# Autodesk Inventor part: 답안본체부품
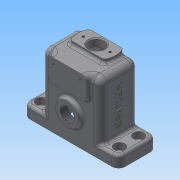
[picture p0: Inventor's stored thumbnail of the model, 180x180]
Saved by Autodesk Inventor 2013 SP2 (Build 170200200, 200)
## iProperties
Created: 2023-12
Part Number: 답안본체부품
Material: Generic
Document SubType Name: Modeling
Designer: i
Density: 1 g/cm^3
Author: i
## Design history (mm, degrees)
sketch "스케치1"
  geometry: L1 (-50, 20)-(50, 20); L2 (50, 20)-(50, -20); L3 (50, -20)-(-50, -20); L4 (-50, -20)-(-50, 20); L5 (-50, 20)-(50, -20); L6 (50, 20)-(-50, -20); 1 further point
  constraints: 12 end point, 2 midpoint, 2 parallel, 1 horizontal, 1 perpendicular
  dimensions: "d0" = 100 distance of L2.end L3.end; "d1" = 40 distance of L1.end L2.end
extrude "돌출1" new body sketch "스케치1" distance "d2" = 12; taper "d3" = 0 deg
sketch "스케치2"
  geometry: L1 (50, 12)-(50, 0) reference; L2 (50, 0)-(-50, 0) reference; L3 (-50, 0)-(-50, 12) reference; L4 (-50, 12)-(50, 12) reference; L5 (50, 12)-(-50, 12) reference; L6 (-31, 12)-(31, 12); L7 (31, 12)-(31, 72); L8 (31, 72)-(-31, 72); L9 (-31, 72)-(-31, 12); 3 further points
  constraints: 8 end point, 2 midpoint, 2 parallel, 1 horizontal, 1 perpendicular, 1 point on line, 1 vertical alignment
  dimensions: "d4" = 62 distance of L7.end L8.end; "d6" = 72 distance between parallel lines of L8 L2
extrude "돌출2" join sketch "스케치2" stored distance "d7" = 40; taper "d9" = 0 deg; dims "d8" = 20, "d10" = 0
sketch "스케치3"
  geometry: L1 (-31, -72)-(31, -72) reference; L2 (20, -72)-(-20, -72); L3 (-20, -72)-(-20, -48); L4 (-20, -48)-(20, -48); L5 (20, -48)-(20, -72); 3 further points
  constraints: 8 end point, 2 midpoint, 2 parallel, 1 horizontal, 1 perpendicular, 1 point on line, 1 vertical alignment
  dimensions: "d11" = 40 distance of L3.end L4.end; "d13" = 24 distance of L2.end L3.end
extrude "돌출3" join sketch "스케치3" distance "d14" = 4; taper "d15" = 0 deg
sketch "스케치4"
  geometry: L1 (0, 0)-(100, 0) reference; L2 (0, -12)-(0, 0) reference; L3 (0, 0)-(100, 0) reference; L4 (100, 0)-(100, -12) reference; L5 (100, -12)-(81, -12) reference; L6 (81, -12)-(81, -72) reference; L7 (81, -72)-(70, -72) reference; L8 (70, -72)-(30, -72) reference; L9 (30, -72)-(19, -72) reference; L10 (19, -72)-(19, -12) reference; L11 (19, -12)-(0, -12) reference; L12 (70, -48)-(70, -72) reference; L13 (30, -48)-(70, -48) reference; L14 (30, -72)-(30, -48) reference; C1 r 12 at (50, -28); 1 further point
  constraints: 1 centre point
  dimensions: "d16" = 28 distance from line of L1 C1.centre; "d17" = 24 diameter of C1
extrude "돌출4" join sketch "스케치4" distance "d18" = 4; taper "d19" = 0 deg
sketch "스케치5"
  geometry: L1 (11, 44)-(51, 44) reference; L2 (55, 3)-(48.321, 3); L3 (7, 3)-(7, 23); L4 (7, 23)-(13.679, 23); L5 (55, 23)-(55, 3); L6 (55, 3)-(7, 23); L7 (7, 3)-(55, 23); L8 (48.321, 3)-(13.679, 3); L9 (48.321, 23)-(55, 23); L10 (13.679, 23)-(48.321, 23); L11 (13.679, 3)-(7, 3); A1 r 20 centre (31, 13) between (48.321, 3) and (48.321, 23); A2 r 20 centre (31, 13) between (13.679, 23) and (13.679, 3); 1 further point
  constraints: 20 end point, 10 parallel, 4 point on circle, 3 horizontal, 3 perpendicular, 2 centre point, 2 midpoint, 1 point on line, 1 vertical alignment
  dimensions: "d22" = 20 distance of L3.start L3.end; "d23" = 31 distance from line of L1 A1.centre; "d24" = 48 distance of L2.start L3.start; "d25" = 20 radius of A2; "d26" = 20 radius of A1
extrude "돌출5" join sketch "스케치5" distance "d27" = 4; taper "d28" = 0 deg
sketch "스케치6"
  geometry: L1 (50, 20)-(50, -20) reference; L2 (50, -20)-(31, -20) reference; L3 (31, 20)-(31, -20) reference; L4 (-31, 20)-(31, 20) reference; L5 (-31, -20)-(-31, 20) reference; L6 (-31, -20)-(-50, -20) reference; L7 (-50, -20)-(-50, 20) reference; L8 (-50, 20)-(-31, 20) reference; L9 (31, 20)-(50, 20) reference; L10 (31, -20)-(-31, -20) reference; L11 (0, 20)-(0, -20); 5 further points
  constraints: 2 end point, 2 midpoint, 2 symmetric about line
  dimensions: "d29" = 20 distance of point (-41, -10) point (-41, 10); "d31" = 10 distance from line of L6 point (-41, -10); "d32" = 82 distance of point (41, 10) point (-41, 10); "d33" = 82 distance of point (41, -10) point (-41, -10)
hole "구멍1" sketch "스케치6" at (-41, 10), (-41, -10), (41, 10), (41, -10) diameter "d34" = 6.6; stored, may be unused: countersink angle "d38" = 90 deg, drill point angle "d40" = 118 deg; dims "d35" = 6.6, "d36" = 11, "d37" = 6.6, "d39" = 8
sketch "스케치7"
  geometry: L1 (100, 0)-(0, 0) reference; C1 r 20 at (50, 28); 2 further points
  constraints: 1 centre point, 1 midpoint, 1 vertical alignment
  dimensions: "d41" = 40 diameter of C1; "d42" = 28 distance from line of C1.centre L1
extrude "돌출6" join sketch "스케치7" distance "d43" = 4; taper "d44" = 0 deg
sketch "스케치8"
  geometry: L1 (-27, 16)-(27, 16); L2 (27, 16)-(27, -16); L3 (27, -16)-(-27, -16); L4 (-27, -16)-(-27, 16); L5 (-27, 16)-(27, -16); L6 (27, 16)-(-27, -16); 1 further point
  constraints: 12 end point, 2 midpoint, 2 parallel, 1 horizontal, 1 perpendicular
  dimensions: "d45" = 32 distance of L1.end L2.end; "d47" = 54 distance of L2.end L3.end
extrude "돌출7" cut sketch "스케치8" distance "d48" = 68; taper "d49" = 0 deg
sketch "스케치9"
  geometry: C1 r 8 at (31, 13); A1 r 20 centre (31, 13) between (13.679, 23) and (13.679, 3) reference; 1 further point
  constraints: 1 centre point, 1 coincident
  dimensions: "d50" = 16 diameter of C1
extrude "돌출8" cut sketch "스케치9" stored distance "d51" = 68; taper "d52" = 0 deg
sketch "스케치10"
  geometry: C1 r 20 at (0, 0) reference; C2 r 9 at (0, 0); 1 further point
  constraints: 1 centre point, 1 coincident
  dimensions: "d53" = 18 diameter of C2
extrude "돌출9" cut sketch "스케치10" stored distance "d54" = 68; taper "d55" = 0 deg
sketch "스케치11" dims "d56" = 30
  geometry: L1 (0, 0)-(0, 15); L2 (0, 0)-(-15, 0); L3 (0, 0)-(0, -15); L4 (0, 0)-(15, 0); C1 r 9 at (0, 0) reference; C2 r 20 at (0, 0) reference; 5 further points
  constraints: 8 end point, 5 coincident, 2 horizontal alignment, 2 vertical alignment, 1 vertical, 29 other
  dimensions: "d59" = 360 deg dimension on C1.centre L1.end (derived)
hole "구멍2" sketch "스케치11" at (0, 15), (-15, 0), (0, -15), (15, 0) diameter "d61" = 2.459; stored, may be unused: countersink angle "d65" = 90 deg, drill point angle "d67" = 118 deg; dims "d62" = 6.6, "d63" = 11, "d64" = 6.6, "d66" = 8
sketch "스케치12"
  geometry: L1 (20, -72)-(31, -72) reference; L2 (-31, -72)-(-20, -72) reference; 3 further points
  dimensions: "d68" = 28 distance of point (-14, -66) point (14, -66); "d70" = 6 distance from line of point (14, -66) L1; "d71" = 6 distance from line of L2 point (-14, -66); "d72" = 14 horizontal distance of point (0, 0) point (14, -66)
hole "구멍3" sketch "스케치12" at (14, -66), (-14, -66) diameter "d73" = 2.459; stored, may be unused: countersink angle "d77" = 90 deg, drill point angle "d79" = 118 deg; dims "d74" = 6.6, "d75" = 11, "d76" = 6.6, "d78" = 8
sketch "스케치13"
  geometry: C1 r 8 at (31, 13) reference; 3 further points
  constraints: 2 horizontal alignment
  dimensions: "d80" = 28 distance of point (17, 13) point (45, 13); "d82" = 14 distance of point (45, 13) C1.centre
hole "구멍4" sketch "스케치13" at (45, 13), (17, 13) diameter "d83" = 2.459; stored, may be unused: countersink angle "d87" = 90 deg, drill point angle "d89" = 118 deg; dims "d84" = 6.6, "d85" = 11, "d86" = 6.6, "d88" = 8
hole "구멍5" diameter "d92" = 14.917; stored, may be unused: countersink angle "d96" = 90 deg, drill point angle "d98" = 118 deg; dims "d93" = 6.6, "d94" = 11, "d95" = 6.6, "d97" = 8, "d99" = 10, "d100" = 10
fillet "모깎기1" dims "d101" = 7
fillet "모깎기5" dims "d105" = 3
fillet "모깎기7" dims "d107" = 3
fillet "모깎기8" dims "d108" = 3
fillet "모깎기10" dims "d110" = 7
fillet "모깎기11" dims "d111" = 7
fillet "모깎기12" dims "d112" = 3
fillet "모깎기13" dims "d113" = 7
fillet "모깎기14" dims "d114" = 3
fillet "모깎기15" dims "d115" = 5
fillet "모깎기16" dims "d116" = 3
fillet "모깎기17" dims "d117" = 3
chamfer "모따기1" distance "d118" = 1; stored, may be unused: second distance "d119" = 2, angle "d120" = 45 deg
sketch "스케치14"
  geometry: L1 (-39.238, 17.002)-(-10.762, 17.002); L2 (-10.762, 17.002)-(-10.762, 10.998); L3 (-10.762, 10.998)-(-39.238, 10.998); L4 (-39.238, 10.998)-(-39.238, 17.002); L5 (-39.238, 14)-(-10.762, 14); L6 (-25, 17.002)-(-25, 10.998); L7 (-65, 0)-(-65, 26) reference; L8 (-25, 37)-(-49, 37) reference; 1 further point
  constraints: 4 end point, 4 midpoint, 2 other
  dimensions: "d121" = 40 distance between parallel lines of L7 L6; "d122" = 23 distance between parallel lines of L8 L5
feature "엠보싱1" sketch "스케치14" dims "d0" = 100, "d1" = 40, "d123" = 0.5, "d124" = 0
node "솔리드1"
node "절단 모서리 투영1"
node "절단 모서리 투영2"
node "절단 모서리 투영3"
